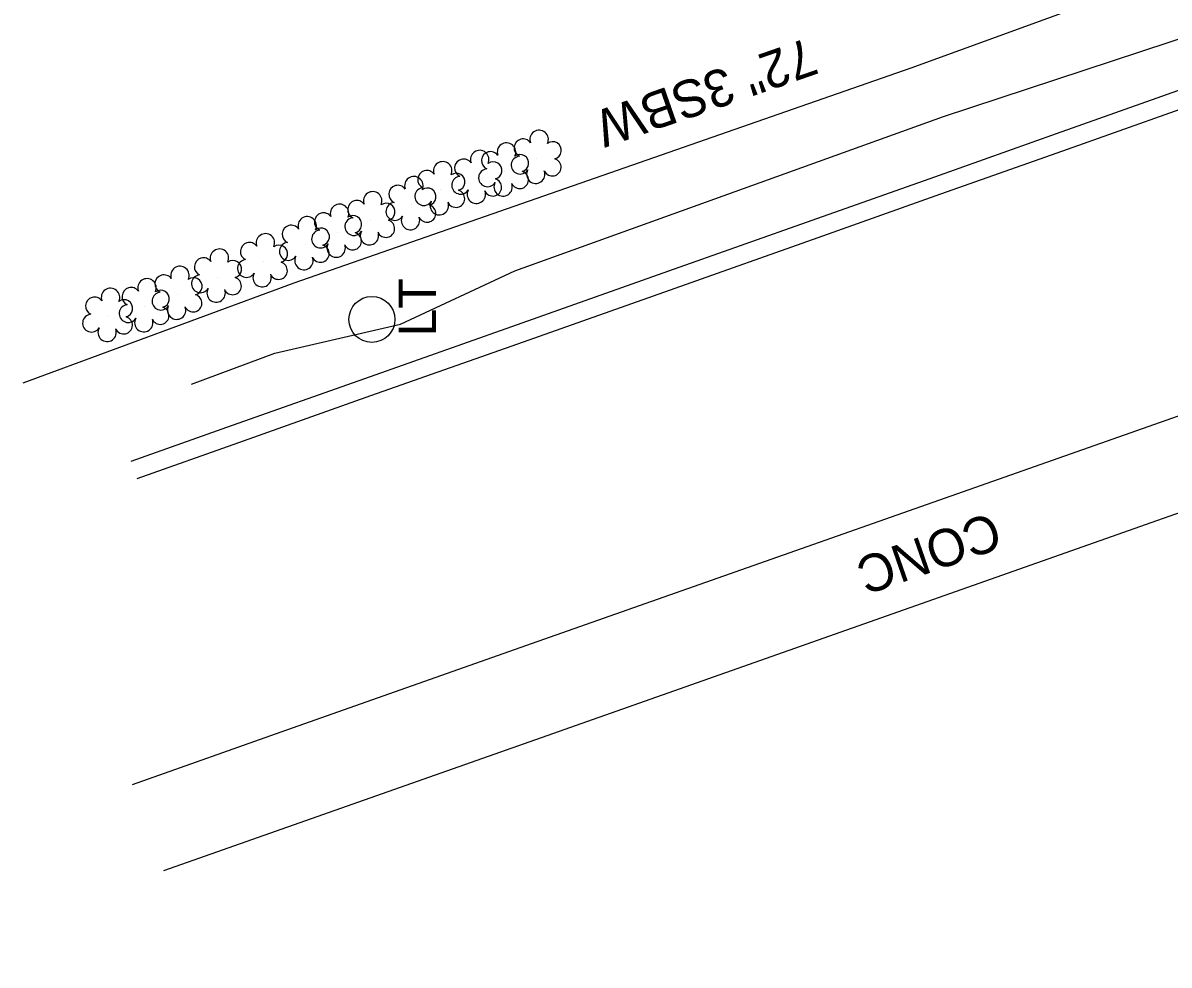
# Model space of a CAD drawing. Extents: x 1614611 to 1617571, y 898867 to 905462.
# Drawn here: x 1615905.9 to 1616028.5, y 903837.4 to 903938.3 of the extents above; entities that cross this region are included whole.
import ezdxf

# ---------------------------------------------------------------- set-up
doc = ezdxf.new("R2010")
doc.units = 0
for name, color, linetype in [('Exist Boundary Watershed Residential C 05', 7, 'Continuous'), ('Exist Other Culture Fence Line', 7, 'Continuous'), ('Exist Other Culture Fence Line Text', 7, 'Continuous'), ('Exist Roads Change in Surface', 7, 'Continuous'), ('Exist Roads Change in Surface Text', 7, 'Continuous'), ('Exist Utilities Other Pole CELL', 7, 'Continuous'), ('Exist Utilities Other Pole Text', 7, 'Continuous'), ('Exist Vegetation Shrub CELL', 7, 'Continuous'), ('Prop Drainage Structure Catch Basin Grate 840 03E Label', 7, 'Continuous'), ('Scratch_Level_1', 7, 'Continuous')]:
    doc.layers.add(name, color=color, linetype=linetype)

msp = doc.modelspace()

# ---------------------------------------------------------------- linework, layer by layer
at = {"layer": 'Exist Boundary Watershed Residential C 05'}
msp.add_lwpolyline([(1616034.54, 903932.81), (1616016.42, 903926.38), (1616003.4, 903921.77), (1615990.28, 903917.11), (1615974.95, 903911.69), (1615958.14, 903905.73), (1615942.42, 903900.19), (1615928.29, 903895.17), (1615917.43, 903891.32)], dxfattribs=at)
at = {"layer": 'Exist Other Culture Fence Line'}
msp.add_lwpolyline([(1616211.35, 903767.58), (1616195.22, 903813.36), (1616186.56, 903825.42), (1616168.75, 903875.81), (1616153.63, 903916.5), (1616129.58, 903932.3), (1616098.05, 903952.43), (1616082.04, 903962.19), (1616045.01, 903949.52), (1616000.86, 903933.41), (1615934.86, 903910.4), (1615905.89, 903899.71)], dxfattribs=at)
at = {"layer": 'Exist Roads Change in Surface'}
for points in [[(1615917.61, 903856.74), (1615934.11, 903862.61), (1615960.99, 903872.11), (1616029.5, 903896.23), (1616058.14, 903906.43), (1616080.48, 903914.29), (1616095.43, 903919.73)], [(1616098.71, 903910.33), (1616077.62, 903902.83), (1616054.59, 903894.66), (1616034.64, 903887.62), (1615960.72, 903861.55), (1615920.92, 903847.5)]]:
    msp.add_lwpolyline(points, dxfattribs=at)
at = {"layer": 'Exist Utilities Other Pole CELL'}
msp.add_circle((1615943.22, 903906.53), 2.46, dxfattribs=at)
at = {"layer": 'Exist Vegetation Shrub CELL'}
for p, q in [((1615960.88, 903923.75), (1615960.88, 903923.75)), ((1615954.53, 903921.6), (1615954.53, 903921.6)), ((1615957.39, 903922.39), (1615957.39, 903922.39)), ((1615950.57, 903920.39), (1615950.57, 903920.39)), ((1615947.48, 903918.8), (1615947.48, 903918.8)), ((1615943.09, 903917.18), (1615943.09, 903917.18)), ((1615939.53, 903915.84), (1615939.53, 903915.84)), ((1615936.08, 903914.51), (1615936.08, 903914.51)), ((1615931.6, 903912.68), (1615931.6, 903912.68)), ((1615926.68, 903911.04), (1615926.68, 903911.04)), ((1615922.46, 903909.2), (1615922.46, 903909.2)), ((1615918.95, 903907.87), (1615918.95, 903907.87)), ((1615915.03, 903906.84), (1615915.03, 903906.84))]:
    msp.add_line(p, q, dxfattribs=at)
for centre, radius, start, end in [((1615961.11, 903925.79), 0.99, 334.8391, 200.4717), ((1615957.62, 903924.44), 0.99, 334.8391, 200.4717), ((1615959.4, 903924.88), 0.968, 35.8908, 245.4216), ((1615962.55, 903924.62), 0.929, 284.4567, 126.0861), ((1615953.04, 903922.73), 0.968, 35.8908, 245.4216), ((1615954.75, 903923.64), 0.99, 334.8391, 200.4717), ((1615955.91, 903923.52), 0.968, 35.8908, 245.4216), ((1615959.08, 903923.04), 0.955, 95.1099, 327.9534), ((1615959.06, 903923.26), 0.929, 284.4567, 126.0861), ((1615962.52, 903922.82), 0.937, 204.9913, 73.4601), ((1615949.09, 903921.51), 0.968, 35.8908, 245.4216), ((1615950.8, 903922.43), 0.99, 334.8391, 200.4717), ((1615955.59, 903921.69), 0.955, 95.1099, 327.9534), ((1615956.2, 903922.47), 0.929, 284.4567, 126.0861), ((1615960.75, 903922.07), 0.984, 151.2797, 21.387), ((1615947.71, 903920.84), 0.99, 334.8391, 200.4717), ((1615952.24, 903921.25), 0.929, 284.4567, 126.0861), ((1615952.72, 903920.89), 0.955, 95.1099, 327.9534), ((1615956.16, 903920.67), 0.937, 204.9913, 73.4601), ((1615959.03, 903921.47), 0.937, 204.9913, 73.4601), ((1615943.31, 903919.22), 0.99, 334.8391, 200.4717), ((1615946, 903919.92), 0.968, 35.8908, 245.4216), ((1615948.77, 903919.68), 0.955, 95.1099, 327.9534), ((1615949.15, 903919.66), 0.929, 284.4567, 126.0861), ((1615952.21, 903919.46), 0.937, 204.9913, 73.4601), ((1615954.4, 903919.92), 0.984, 151.2797, 21.387), ((1615957.26, 903920.71), 0.984, 151.2797, 21.387), ((1615939.76, 903917.88), 0.99, 334.8391, 200.4717), ((1615941.6, 903918.3), 0.968, 35.8908, 245.4216), ((1615944.76, 903918.04), 0.929, 284.4567, 126.0861), ((1615945.68, 903918.09), 0.955, 95.1099, 327.9534), ((1615949.12, 903917.87), 0.937, 204.9913, 73.4601), ((1615950.44, 903918.7), 0.984, 151.2797, 21.387), ((1615936.31, 903916.55), 0.99, 334.8391, 200.4717), ((1615938.04, 903916.97), 0.968, 35.8908, 245.4216), ((1615941.2, 903916.71), 0.929, 284.4567, 126.0861), ((1615947.35, 903917.11), 0.984, 151.2797, 21.387), ((1615934.6, 903915.64), 0.968, 35.8908, 245.4216), ((1615937.75, 903915.38), 0.929, 284.4567, 126.0861), ((1615941.29, 903916.47), 0.955, 95.1099, 327.9534), ((1615944.72, 903916.25), 0.937, 204.9913, 73.4601), ((1615931.83, 903914.72), 0.99, 334.8391, 200.4717), ((1615937.73, 903915.14), 0.955, 95.1099, 327.9534), ((1615941.16, 903914.91), 0.937, 204.9913, 73.4601), ((1615942.96, 903915.49), 0.984, 151.2797, 21.387), ((1615926.91, 903913.08), 0.99, 334.8391, 200.4717), ((1615930.12, 903913.81), 0.968, 35.8908, 245.4216), ((1615933.28, 903913.55), 0.929, 284.4567, 126.0861), ((1615934.28, 903913.81), 0.955, 95.1099, 327.9534), ((1615937.72, 903913.58), 0.937, 204.9913, 73.4601), ((1615939.4, 903914.16), 0.984, 151.2797, 21.387), ((1615925.2, 903912.17), 0.968, 35.8908, 245.4216), ((1615928.36, 903911.91), 0.929, 284.4567, 126.0861), ((1615929.8, 903911.98), 0.955, 95.1099, 327.9534), ((1615933.24, 903911.75), 0.937, 204.9913, 73.4601), ((1615935.95, 903912.83), 0.984, 151.2797, 21.387), ((1615922.69, 903911.24), 0.99, 334.8391, 200.4717), ((1615931.48, 903911), 0.984, 151.2797, 21.387), ((1615919.17, 903909.91), 0.99, 334.8391, 200.4717), ((1615920.98, 903910.33), 0.968, 35.8908, 245.4216), ((1615924.13, 903910.07), 0.929, 284.4567, 126.0861), ((1615924.88, 903910.34), 0.955, 95.1099, 327.9534), ((1615928.32, 903910.11), 0.937, 204.9913, 73.4601), ((1615915.26, 903908.88), 0.99, 334.8391, 200.4717), ((1615917.46, 903908.99), 0.968, 35.8908, 245.4216), ((1615920.66, 903908.49), 0.955, 95.1099, 327.9534), ((1615920.62, 903908.73), 0.929, 284.4567, 126.0861), ((1615924.1, 903908.27), 0.937, 204.9913, 73.4601), ((1615926.56, 903909.36), 0.984, 151.2797, 21.387), ((1615913.55, 903907.96), 0.968, 35.8908, 245.4216), ((1615916.7, 903907.71), 0.929, 284.4567, 126.0861), ((1615917.15, 903907.16), 0.955, 95.1099, 327.9534), ((1615920.58, 903906.94), 0.937, 204.9913, 73.4601), ((1615922.33, 903907.52), 0.984, 151.2797, 21.387), ((1615913.23, 903906.13), 0.955, 95.1099, 327.9534), ((1615916.67, 903905.91), 0.937, 204.9913, 73.4601), ((1615918.82, 903906.18), 0.984, 151.2797, 21.387), ((1615914.9, 903905.15), 0.984, 151.2797, 21.387)]:
    msp.add_arc(centre, radius, start, end, dxfattribs=at)
at = {"layer": 'Prop Drainage Structure Catch Basin Grate 840 03E Label'}
msp.add_lwpolyline([(1615923.93, 903899.6), (1615932.83, 903902.93), (1615946.29, 903906.03), (1615958.51, 903911.73), (1616004.36, 903928.24), (1616037.61, 903939.19), (1616040.41, 903939.94), (1616059.29, 903947.07), (1616082.31, 903953.27), (1616090.33, 903952.53), (1616098.78, 903948.15), (1616126.18, 903929.2), (1616146.2, 903914.72), (1616149.01, 903912.2)], dxfattribs=at)
at = {"layer": 'Scratch_Level_1'}
msp.add_lwpolyline([(1616035.19, 903930.97), (1616017.08, 903924.53), (1616004.06, 903919.93), (1615990.93, 903915.27), (1615975.61, 903909.85), (1615958.79, 903903.88), (1615943.08, 903898.34), (1615928.94, 903893.33), (1615918.09, 903889.48)], dxfattribs=at)

# ---------------------------------------------------------------- texts
at = {"layer": 'Exist Other Culture Fence Line Text'}
msp.add_text('72" 3SBW', height=4, rotation=199.2211, dxfattribs=at).set_placement((1615989.91, 903936.73))
at = {"layer": 'Exist Roads Change in Surface Text'}
msp.add_text('CONC', height=4, rotation=199.1891, dxfattribs=at).set_placement((1616009.61, 903885.97))
at = {"layer": 'Exist Utilities Other Pole Text'}
msp.add_text('LT', height=4, rotation=90, dxfattribs=at).set_placement((1615950.08, 903904.71))

doc.saveas('drawing.dxf')
